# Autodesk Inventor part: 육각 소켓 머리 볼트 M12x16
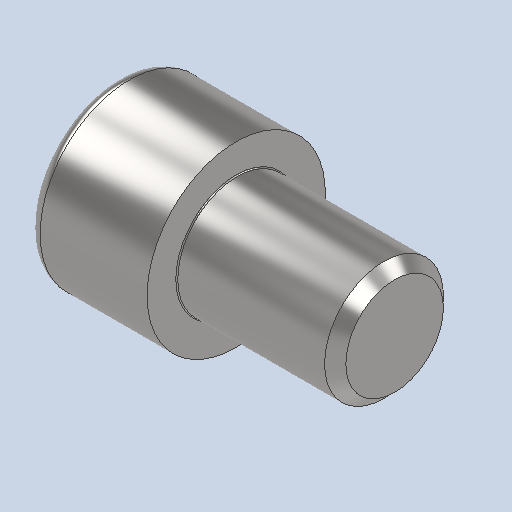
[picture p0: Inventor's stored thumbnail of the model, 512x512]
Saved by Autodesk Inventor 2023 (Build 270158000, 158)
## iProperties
Created: 2024-07
Part Number: 육각 소켓 머리 볼트 M12x16
Material: 강철, 연강
Description: 6각머리 태핑 나사
Document SubType Name: Modeling
Designer: home
Density: 7.85 g/cm^3
Appearance: 기본값
Author: jhkim
Sending System: Autodesk Inventor 2025
Preprocessor: ST-DEVELOPER v20
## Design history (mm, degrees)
feature "Solid1"
node "솔리드1"
